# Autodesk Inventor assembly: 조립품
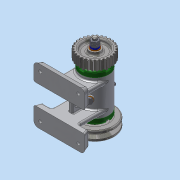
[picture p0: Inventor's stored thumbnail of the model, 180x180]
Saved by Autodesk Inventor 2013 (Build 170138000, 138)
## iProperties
Created: 2016-07
Part Number: 조립품
Document SubType Name: Assembly
Designer: dgall
Author: dgall
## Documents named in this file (16)
- C:\Users\dgall\Desktop\460707V1012\조립품.iam
- C:\Users\dgall\Desktop\460707V1012\본체.ipt
- C:\Users\dgall\Desktop\460707V1012\커버.ipt
- C:\Users\dgall\Desktop\460707V1012\축.ipt
- C:\Users\dgall\Desktop\460707V1012\베어링 15 x 32 x 9.ipt
- C:\Users\dgall\Desktop\460707V1012\키 3 x 3 x 12.ipt
- C:\Users\dgall\Desktop\460707V1012\스퍼기어.ipt
- C:\Users\dgall\Desktop\460707V1012\V벨트풀리.ipt
- C:\Users\dgall\Desktop\460707V1012\오일 실 15 25 7.ipt
- C:\Users\dgall\Desktop\460707V1012\볼트 M4 x 12.ipt
- C:\Users\dgall\Desktop\460707V1012\니플 M 6 x 0.75.ipt
- C:\Users\dgall\Desktop\460707V1012\볼트 M 6 x 8.ipt
- C:\Users\dgall\Desktop\460707V1012\와셔 6x11.5.ipt
- C:\Users\dgall\Desktop\460707V1012\스프링와셔 8.ipt
- C:\Users\dgall\Desktop\460707V1012\와셔 8x17.ipt
- C:\Users\dgall\Desktop\460707V1012\너트 M 8.ipt
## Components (11 placed, 3 different names)
1. KS B 2023 6002 - 15 x 32 x 9:1
2. KS B 2023 6002 - 15 x 32 x 9:2
3. V벨트풀리:1
4. ISO 4762 M4 x 12:1
5. ISO 4762 M4 x 12:2
6. ISO 4762 M4 x 12:3
7. ISO 4762 M4 x 12:4
8. ISO 4762 M4 x 12:5
9. ISO 4762 M4 x 12:6
10. ISO 4762 M4 x 12:7
11. ISO 4762 M4 x 12:8
